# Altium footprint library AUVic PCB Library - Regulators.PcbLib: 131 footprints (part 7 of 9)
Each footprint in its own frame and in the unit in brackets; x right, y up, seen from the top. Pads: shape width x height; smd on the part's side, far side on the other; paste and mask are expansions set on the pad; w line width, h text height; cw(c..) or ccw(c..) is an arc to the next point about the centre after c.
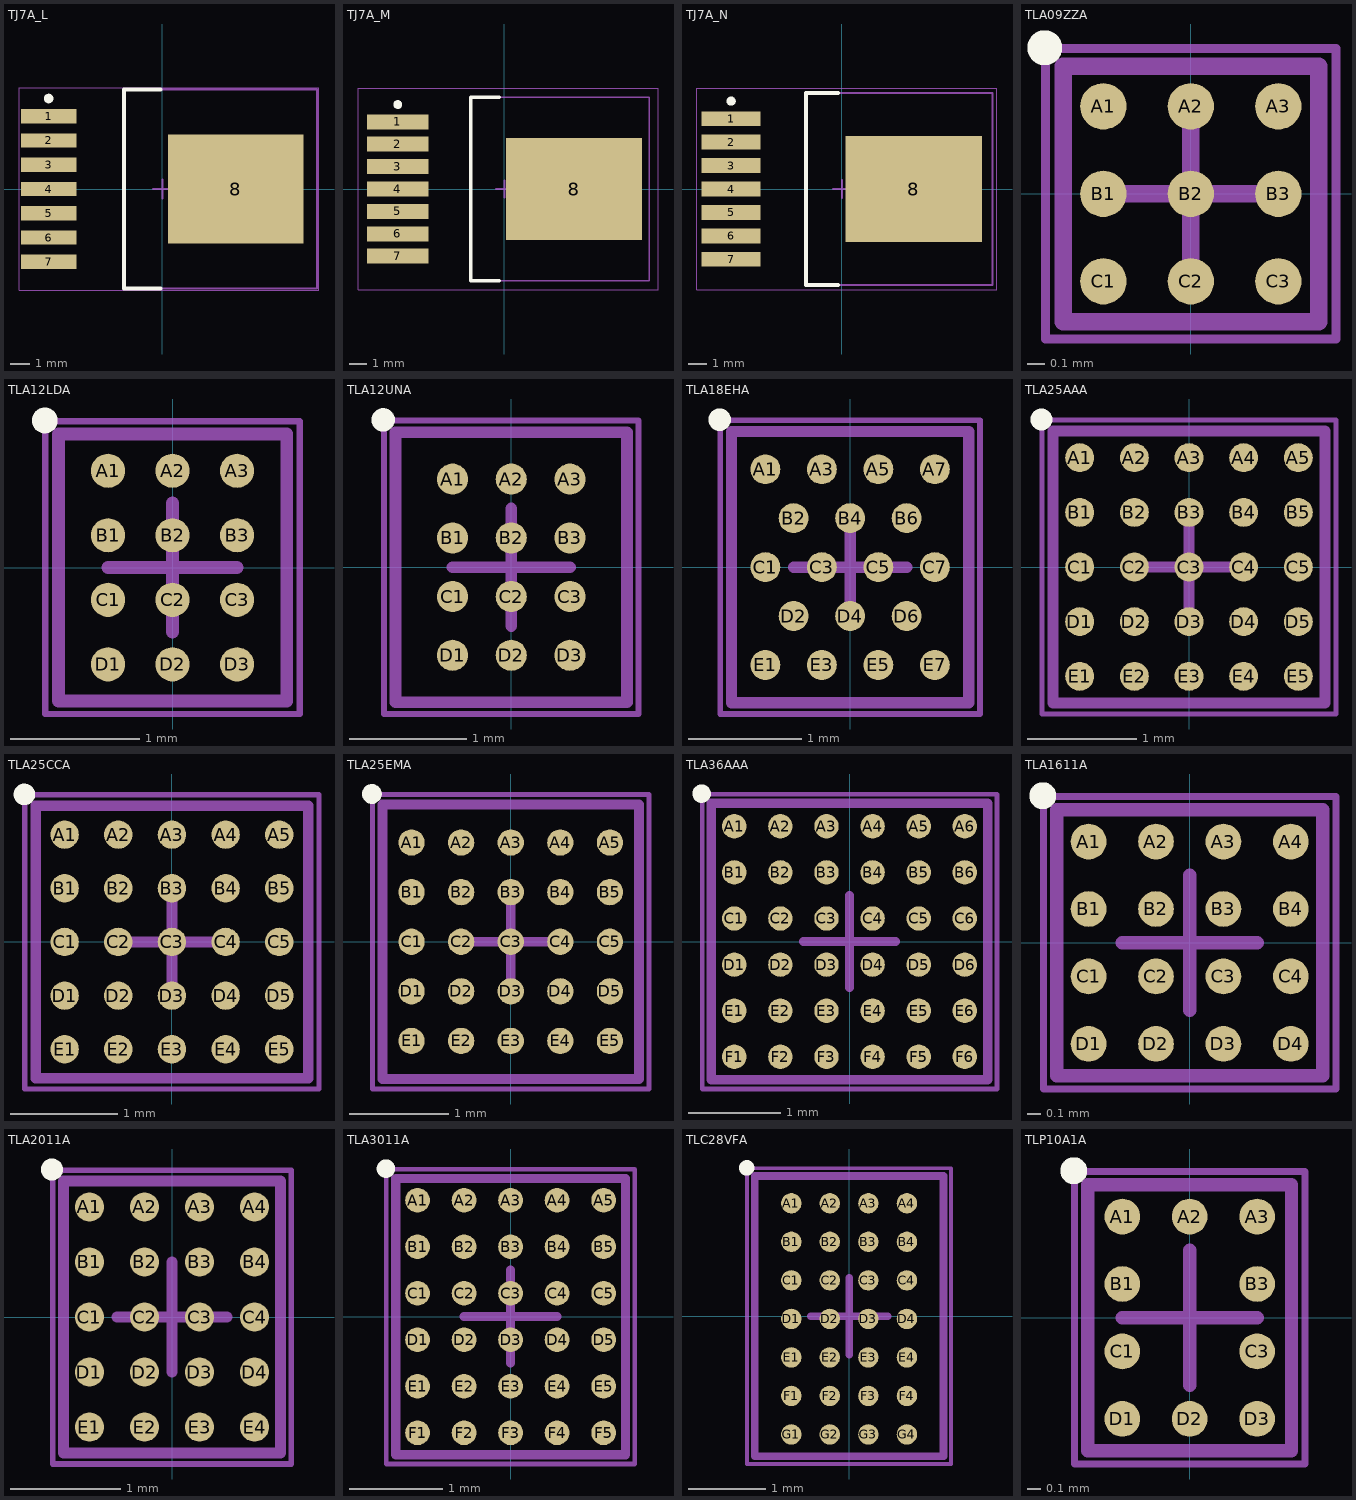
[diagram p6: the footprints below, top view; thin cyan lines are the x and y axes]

## TJ7A_L [mm] "D2-PAK, 8-Leads, Body 9.9x10.2mm, Pitch 1.27mm, Lead Span 14mm, IPC High Density"
height 2.1
pads (8):
  rect 2.9x0.75 smd: 1(-5.95,3.81) 2(-5.95,2.54) 3(-5.95,1.27) 4(-5.95,0) 5(-5.95,-1.27) 6(-5.95,-2.54) 7(-5.95,-3.81)
  rect 7.1x5.7 smd: 8(3.85,0)
Top Overlay:
  circle w0.25: c-5.95,4.735 r0.125
  lines w0.2: -0.1,-5.2 -2,-5.2 -2,5.2 -0.1,5.2
Mechanical 13:
  lines w0.1: -2,-5.2 8.1,-5.2 8.1,5.2 -2,5.2 -2,-5.2
Mechanical 15:
  lines w0.05: -7.5,-5.3 8.2,-5.3 8.2,5.3 -7.5,5.3 -7.5,-5.3
  lines w0.1: -0.5,0 0.5,0 ; 0,-0.5 0,0.5
3D body: height 2.1, standoff 0, extent -2,-5.2 8.1,5.2

## TJ7A_M [mm] "D2-PAK, 8-Leads, Body 9.9x10.2mm, Pitch 1.27mm, Lead Span 14mm, IPC Low Density"
height 2.1
pads (8):
  rect 3.5x0.85 smd: 1(-6.05,3.81) 2(-6.05,2.54) 3(-6.05,1.27) 4(-6.05,0) 5(-6.05,-1.27) 6(-6.05,-2.54) 7(-6.05,-3.81)
  rect 7.7x5.8 smd: 8(3.95,0)
Top Overlay:
  circle w0.25: c-6.05,4.785 r0.125
  lines w0.2: -0.3,-5.2 -1.9,-5.2 -1.9,5.2 -0.3,5.2
Mechanical 13:
  lines w0.1: -1.9,-5.2 8.2,-5.2 8.2,5.2 -1.9,5.2 -1.9,-5.2
Mechanical 15:
  lines w0.05: -8.3,-5.7 8.7,-5.7 8.7,5.7 -8.3,5.7 -8.3,-5.7
  lines w0.1: -0.5,0 0.5,0 ; 0,-0.5 0,0.5
3D body: height 2.1, standoff 0, extent -1.9,-5.2 8.2,5.2

## TJ7A_N [mm] "D2-PAK, 8-Leads, Body 9.9x10.2mm, Pitch 1.27mm, Lead Span 14mm, IPC Medium Density"
height 2.1
pads (8):
  rect 3.2x0.8 smd: 1(-6,3.81) 2(-6,2.54) 3(-6,1.27) 4(-6,0) 5(-6,-1.27) 6(-6,-2.54) 7(-6,-3.81)
  rect 7.4x5.75 smd: 8(3.9,0)
Top Overlay:
  circle w0.25: c-6,4.76 r0.125
  lines w0.2: -0.2,-5.2 -1.95,-5.2 -1.95,5.2 -0.2,5.2
Mechanical 13:
  lines w0.1: -1.95,-5.2 8.15,-5.2 8.15,5.2 -1.95,5.2 -1.95,-5.2
Mechanical 15:
  lines w0.05: -7.85,-5.45 8.4,-5.45 8.4,5.45 -7.85,5.45 -7.85,-5.45
  lines w0.1: -0.5,0 0.5,0 ; 0,-0.5 0,0.5
3D body: height 2.1, standoff 0, extent -1.95,-5.2 8.15,5.2

## TLA09ZZA [mm] "Micro SMD, 9-Leads, Body 1.47x1.47mm, Pitch 0.5mm, NSC Recommended"
height 0.68
pads (9):
  round 0.265 smd paste-0.132 mask+0.05: A1(-0.5,0.5) A2(0,0.5) A3(0.5,0.5) B1(-0.5,0) B2(0,0) B3(0.5,0) C1(-0.5,-0.5) C2(0,-0.5) C3(0.5,-0.5)
Top Overlay:
  circle w0.1: c-0.835,0.835 r0.05
Top Paste:
  circle w0.05: c-0.575,0.425 r0.025
  circle w0.05: c-0.425,0.575 r0.025
  circle w0.05: c-0.425,0.425 r0.025
  circle w0.05: c-0.575,0.575 r0.025
  circle w0.05: c-0.075,0.425 r0.025
  circle w0.05: c0.075,0.575 r0.025
  circle w0.05: c0.075,0.425 r0.025
  circle w0.05: c-0.075,0.575 r0.025
  circle w0.05: c0.425,0.425 r0.025
  circle w0.05: c0.575,0.575 r0.025
  circle w0.05: c0.575,0.425 r0.025
  circle w0.05: c0.425,0.575 r0.025
  circle w0.05: c-0.575,-0.075 r0.025
  circle w0.05: c-0.425,0.075 r0.025
  circle w0.05: c-0.425,-0.075 r0.025
  circle w0.05: c-0.575,0.075 r0.025
  circle w0.05: c-0.075,-0.075 r0.025
  circle w0.05: c0.075,0.075 r0.025
  circle w0.05: c0.075,-0.075 r0.025
  circle w0.05: c-0.075,0.075 r0.025
  circle w0.05: c0.425,-0.075 r0.025
  circle w0.05: c0.575,0.075 r0.025
  circle w0.05: c0.575,-0.075 r0.025
  circle w0.05: c0.425,0.075 r0.025
  circle w0.05: c-0.575,-0.575 r0.025
  circle w0.05: c-0.425,-0.425 r0.025
  circle w0.05: c-0.425,-0.575 r0.025
  circle w0.05: c-0.575,-0.425 r0.025
  circle w0.05: c-0.075,-0.575 r0.025
  circle w0.05: c0.075,-0.425 r0.025
  circle w0.05: c0.075,-0.575 r0.025
  circle w0.05: c-0.075,-0.425 r0.025
  circle w0.05: c0.425,-0.575 r0.025
  circle w0.05: c0.575,-0.425 r0.025
  circle w0.05: c0.575,-0.575 r0.025
  circle w0.05: c0.425,-0.425 r0.025
  region: -0.575,0.575 -0.575,0.425 -0.425,0.425 -0.425,0.575
  region: -0.575,0.425 -0.575,0.575 -0.625,0.575 -0.625,0.425
  rectangle: -0.575,0.575 -0.425,0.625
  region: -0.425,0.575 -0.425,0.425 -0.375,0.425 -0.375,0.575
  region: -0.425,0.425 -0.575,0.425 -0.575,0.375 -0.425,0.375
  region: -0.075,0.575 -0.075,0.425 0.075,0.425 0.075,0.575
  region: -0.075,0.425 -0.075,0.575 -0.125,0.575 -0.125,0.425
  rectangle: -0.075,0.575 0.075,0.625
  region: 0.075,0.575 0.075,0.425 0.125,0.425 0.125,0.575
  region: 0.075,0.425 -0.075,0.425 -0.075,0.375 0.075,0.375
  region: 0.425,0.575 0.425,0.425 0.575,0.425 0.575,0.575
  region: 0.425,0.425 0.425,0.575 0.375,0.575 0.375,0.425
  rectangle: 0.425,0.575 0.575,0.625
  region: 0.575,0.575 0.575,0.425 0.625,0.425 0.625,0.575
  region: 0.575,0.425 0.425,0.425 0.425,0.375 0.575,0.375
  region: -0.575,0.075 -0.575,-0.075 -0.425,-0.075 -0.425,0.075
  region: -0.575,-0.075 -0.575,0.075 -0.625,0.075 -0.625,-0.075
  rectangle: -0.575,0.075 -0.425,0.125
  region: -0.425,0.075 -0.425,-0.075 -0.375,-0.075 -0.375,0.075
  region: -0.425,-0.075 -0.575,-0.075 -0.575,-0.125 -0.425,-0.125
  region: -0.075,0.075 -0.075,-0.075 0.075,-0.075 0.075,0.075
  region: -0.075,-0.075 -0.075,0.075 -0.125,0.075 -0.125,-0.075
  rectangle: -0.075,0.075 0.075,0.125
  region: 0.075,0.075 0.075,-0.075 0.125,-0.075 0.125,0.075
  region: 0.075,-0.075 -0.075,-0.075 -0.075,-0.125 0.075,-0.125
  region: 0.425,0.075 0.425,-0.075 0.575,-0.075 0.575,0.075
  region: 0.425,-0.075 0.425,0.075 0.375,0.075 0.375,-0.075
  rectangle: 0.425,0.075 0.575,0.125
  region: 0.575,0.075 0.575,-0.075 0.625,-0.075 0.625,0.075
  region: 0.575,-0.075 0.425,-0.075 0.425,-0.125 0.575,-0.125
  region: -0.575,-0.425 -0.575,-0.575 -0.425,-0.575 -0.425,-0.425
  region: -0.575,-0.575 -0.575,-0.425 -0.625,-0.425 -0.625,-0.575
  rectangle: -0.575,-0.425 -0.425,-0.375
  region: -0.425,-0.425 -0.425,-0.575 -0.375,-0.575 -0.375,-0.425
  region: -0.425,-0.575 -0.575,-0.575 -0.575,-0.625 -0.425,-0.625
  region: -0.075,-0.425 -0.075,-0.575 0.075,-0.575 0.075,-0.425
  region: -0.075,-0.575 -0.075,-0.425 -0.125,-0.425 -0.125,-0.575
  rectangle: -0.075,-0.425 0.075,-0.375
  region: 0.075,-0.425 0.075,-0.575 0.125,-0.575 0.125,-0.425
  region: 0.075,-0.575 -0.075,-0.575 -0.075,-0.625 0.075,-0.625
  region: 0.425,-0.425 0.425,-0.575 0.575,-0.575 0.575,-0.425
  region: 0.425,-0.575 0.425,-0.425 0.375,-0.425 0.375,-0.575
  rectangle: 0.425,-0.425 0.575,-0.375
  region: 0.575,-0.425 0.575,-0.575 0.625,-0.575 0.625,-0.425
  region: 0.575,-0.575 0.425,-0.575 0.425,-0.625 0.575,-0.625
Mechanical 13:
  lines w0.1: -0.73,-0.73 -0.73,0.73 0.73,0.73 0.73,-0.73 -0.73,-0.73
Mechanical 15:
  lines w0.05: -0.83,-0.83 -0.83,0.83 0.83,0.83 0.83,-0.83 -0.83,-0.83
  lines w0.1: -0.5,0 0.5,0 ; 0,-0.5 0,0.5
3D body: height 0.68, standoff 0, extent -0.73,-0.73 0.73,0.73

## TLA12LDA [mm] "Micro SMD, 12-Leads, Body 2.07x1.77mm, Pitch 0.5mm, NSC Recommended"
height 0.68
pads (12):
  round 0.265 smd paste-0.132 mask+0.05: A1(-0.5,0.75) A2(0,0.75) A3(0.5,0.75) B1(-0.5,0.25) B2(0,0.25) B3(0.5,0.25) C1(-0.5,-0.25) C2(0,-0.25) C3(0.5,-0.25) D1(-0.5,-0.75) D2(0,-0.75) D3(0.5,-0.75)
Top Overlay:
  circle w0.1: c-0.99,1.14 r0.05
Top Paste:
  circle w0.05: c-0.575,0.675 r0.025
  circle w0.05: c-0.425,0.825 r0.025
  circle w0.05: c-0.425,0.675 r0.025
  circle w0.05: c-0.575,0.825 r0.025
  circle w0.05: c-0.075,0.675 r0.025
  circle w0.05: c0.075,0.825 r0.025
  circle w0.05: c0.075,0.675 r0.025
  circle w0.05: c-0.075,0.825 r0.025
  circle w0.05: c0.425,0.675 r0.025
  circle w0.05: c0.575,0.825 r0.025
  circle w0.05: c0.575,0.675 r0.025
  circle w0.05: c0.425,0.825 r0.025
  circle w0.05: c-0.575,0.175 r0.025
  circle w0.05: c-0.425,0.325 r0.025
  circle w0.05: c-0.425,0.175 r0.025
  circle w0.05: c-0.575,0.325 r0.025
  circle w0.05: c-0.075,0.175 r0.025
  circle w0.05: c0.075,0.325 r0.025
  circle w0.05: c0.075,0.175 r0.025
  circle w0.05: c-0.075,0.325 r0.025
  circle w0.05: c0.425,0.175 r0.025
  circle w0.05: c0.575,0.325 r0.025
  circle w0.05: c0.575,0.175 r0.025
  circle w0.05: c0.425,0.325 r0.025
  circle w0.05: c-0.575,-0.325 r0.025
  circle w0.05: c-0.425,-0.175 r0.025
  circle w0.05: c-0.425,-0.325 r0.025
  circle w0.05: c-0.575,-0.175 r0.025
  circle w0.05: c-0.075,-0.325 r0.025
  circle w0.05: c0.075,-0.175 r0.025
  circle w0.05: c0.075,-0.325 r0.025
  circle w0.05: c-0.075,-0.175 r0.025
  circle w0.05: c0.425,-0.325 r0.025
  circle w0.05: c0.575,-0.175 r0.025
  circle w0.05: c0.575,-0.325 r0.025
  circle w0.05: c0.425,-0.175 r0.025
  circle w0.05: c-0.575,-0.825 r0.025
  circle w0.05: c-0.425,-0.675 r0.025
  circle w0.05: c-0.425,-0.825 r0.025
  circle w0.05: c-0.575,-0.675 r0.025
  circle w0.05: c-0.075,-0.825 r0.025
  circle w0.05: c0.075,-0.675 r0.025
  circle w0.05: c0.075,-0.825 r0.025
  circle w0.05: c-0.075,-0.675 r0.025
  circle w0.05: c0.425,-0.825 r0.025
  circle w0.05: c0.575,-0.675 r0.025
  circle w0.05: c0.575,-0.825 r0.025
  circle w0.05: c0.425,-0.675 r0.025
  region: -0.575,0.825 -0.575,0.675 -0.425,0.675 -0.425,0.825
  region: -0.575,0.675 -0.575,0.825 -0.625,0.825 -0.625,0.675
  rectangle: -0.575,0.825 -0.425,0.875
  region: -0.425,0.825 -0.425,0.675 -0.375,0.675 -0.375,0.825
  region: -0.425,0.675 -0.575,0.675 -0.575,0.625 -0.425,0.625
  region: -0.075,0.825 -0.075,0.675 0.075,0.675 0.075,0.825
  region: -0.075,0.675 -0.075,0.825 -0.125,0.825 -0.125,0.675
  rectangle: -0.075,0.825 0.075,0.875
  region: 0.075,0.825 0.075,0.675 0.125,0.675 0.125,0.825
  region: 0.075,0.675 -0.075,0.675 -0.075,0.625 0.075,0.625
  region: 0.425,0.825 0.425,0.675 0.575,0.675 0.575,0.825
  region: 0.425,0.675 0.425,0.825 0.375,0.825 0.375,0.675
  rectangle: 0.425,0.825 0.575,0.875
  region: 0.575,0.825 0.575,0.675 0.625,0.675 0.625,0.825
  region: 0.575,0.675 0.425,0.675 0.425,0.625 0.575,0.625
  region: -0.575,0.325 -0.575,0.175 -0.425,0.175 -0.425,0.325
  region: -0.575,0.175 -0.575,0.325 -0.625,0.325 -0.625,0.175
  rectangle: -0.575,0.325 -0.425,0.375
  region: -0.425,0.325 -0.425,0.175 -0.375,0.175 -0.375,0.325
  region: -0.425,0.175 -0.575,0.175 -0.575,0.125 -0.425,0.125
  region: -0.075,0.325 -0.075,0.175 0.075,0.175 0.075,0.325
  region: -0.075,0.175 -0.075,0.325 -0.125,0.325 -0.125,0.175
  rectangle: -0.075,0.325 0.075,0.375
  region: 0.075,0.325 0.075,0.175 0.125,0.175 0.125,0.325
  region: 0.075,0.175 -0.075,0.175 -0.075,0.125 0.075,0.125
  region: 0.425,0.325 0.425,0.175 0.575,0.175 0.575,0.325
  region: 0.425,0.175 0.425,0.325 0.375,0.325 0.375,0.175
  rectangle: 0.425,0.325 0.575,0.375
  region: 0.575,0.325 0.575,0.175 0.625,0.175 0.625,0.325
  region: 0.575,0.175 0.425,0.175 0.425,0.125 0.575,0.125
  region: -0.575,-0.175 -0.575,-0.325 -0.425,-0.325 -0.425,-0.175
  region: -0.575,-0.325 -0.575,-0.175 -0.625,-0.175 -0.625,-0.325
  rectangle: -0.575,-0.175 -0.425,-0.125
  region: -0.425,-0.175 -0.425,-0.325 -0.375,-0.325 -0.375,-0.175
  region: -0.425,-0.325 -0.575,-0.325 -0.575,-0.375 -0.425,-0.375
  region: -0.075,-0.175 -0.075,-0.325 0.075,-0.325 0.075,-0.175
  region: -0.075,-0.325 -0.075,-0.175 -0.125,-0.175 -0.125,-0.325
  rectangle: -0.075,-0.175 0.075,-0.125
  region: 0.075,-0.175 0.075,-0.325 0.125,-0.325 0.125,-0.175
  region: 0.075,-0.325 -0.075,-0.325 -0.075,-0.375 0.075,-0.375
  region: 0.425,-0.175 0.425,-0.325 0.575,-0.325 0.575,-0.175
  region: 0.425,-0.325 0.425,-0.175 0.375,-0.175 0.375,-0.325
  rectangle: 0.425,-0.175 0.575,-0.125
  region: 0.575,-0.175 0.575,-0.325 0.625,-0.325 0.625,-0.175
  region: 0.575,-0.325 0.425,-0.325 0.425,-0.375 0.575,-0.375
  region: -0.575,-0.675 -0.575,-0.825 -0.425,-0.825 -0.425,-0.675
  region: -0.575,-0.825 -0.575,-0.675 -0.625,-0.675 -0.625,-0.825
  rectangle: -0.575,-0.675 -0.425,-0.625
  region: -0.425,-0.675 -0.425,-0.825 -0.375,-0.825 -0.375,-0.675
  region: -0.425,-0.825 -0.575,-0.825 -0.575,-0.875 -0.425,-0.875
  region: -0.075,-0.675 -0.075,-0.825 0.075,-0.825 0.075,-0.675
  region: -0.075,-0.825 -0.075,-0.675 -0.125,-0.675 -0.125,-0.825
  rectangle: -0.075,-0.675 0.075,-0.625
  region: 0.075,-0.675 0.075,-0.825 0.125,-0.825 0.125,-0.675
  region: 0.075,-0.825 -0.075,-0.825 -0.075,-0.875 0.075,-0.875
  region: 0.425,-0.675 0.425,-0.825 0.575,-0.825 0.575,-0.675
  region: 0.425,-0.825 0.425,-0.675 0.375,-0.675 0.375,-0.825
  rectangle: 0.425,-0.675 0.575,-0.625
  region: 0.575,-0.675 0.575,-0.825 0.625,-0.825 0.625,-0.675
  region: 0.575,-0.825 0.425,-0.825 0.425,-0.875 0.575,-0.875
Mechanical 13:
  lines w0.1: -0.885,-1.035 -0.885,1.035 0.885,1.035 0.885,-1.035 -0.885,-1.035
Mechanical 15:
  lines w0.05: -0.985,-1.135 -0.985,1.135 0.985,1.135 0.985,-1.135 -0.985,-1.135
  lines w0.1: -0.5,0 0.5,0 ; 0,-0.5 0,0.5
3D body: height 0.68, standoff 0, extent -0.885,-1.035 0.885,1.035

## TLA12UNA [mm] "Micro SMD, 12-Leads, Body 2.3x1.97mm, Pitch 0.5mm, NSC Recommended"
height 0.68
pads (12):
  round 0.265 smd paste-0.132 mask+0.05: A1(-0.5,0.75) A2(0,0.75) A3(0.5,0.75) B1(-0.5,0.25) B2(0,0.25) B3(0.5,0.25) C1(-0.5,-0.25) C2(0,-0.25) C3(0.5,-0.25) D1(-0.5,-0.75) D2(0,-0.75) D3(0.5,-0.75)
Top Overlay:
  circle w0.1: c-1.09,1.255 r0.05
Top Paste:
  circle w0.05: c-0.575,0.675 r0.025
  circle w0.05: c-0.425,0.825 r0.025
  circle w0.05: c-0.425,0.675 r0.025
  circle w0.05: c-0.575,0.825 r0.025
  circle w0.05: c-0.075,0.675 r0.025
  circle w0.05: c0.075,0.825 r0.025
  circle w0.05: c0.075,0.675 r0.025
  circle w0.05: c-0.075,0.825 r0.025
  circle w0.05: c0.425,0.675 r0.025
  circle w0.05: c0.575,0.825 r0.025
  circle w0.05: c0.575,0.675 r0.025
  circle w0.05: c0.425,0.825 r0.025
  circle w0.05: c-0.575,0.175 r0.025
  circle w0.05: c-0.425,0.325 r0.025
  circle w0.05: c-0.425,0.175 r0.025
  circle w0.05: c-0.575,0.325 r0.025
  circle w0.05: c-0.075,0.175 r0.025
  circle w0.05: c0.075,0.325 r0.025
  circle w0.05: c0.075,0.175 r0.025
  circle w0.05: c-0.075,0.325 r0.025
  circle w0.05: c0.425,0.175 r0.025
  circle w0.05: c0.575,0.325 r0.025
  circle w0.05: c0.575,0.175 r0.025
  circle w0.05: c0.425,0.325 r0.025
  circle w0.05: c-0.575,-0.325 r0.025
  circle w0.05: c-0.425,-0.175 r0.025
  circle w0.05: c-0.425,-0.325 r0.025
  circle w0.05: c-0.575,-0.175 r0.025
  circle w0.05: c-0.075,-0.325 r0.025
  circle w0.05: c0.075,-0.175 r0.025
  circle w0.05: c0.075,-0.325 r0.025
  circle w0.05: c-0.075,-0.175 r0.025
  circle w0.05: c0.425,-0.325 r0.025
  circle w0.05: c0.575,-0.175 r0.025
  circle w0.05: c0.575,-0.325 r0.025
  circle w0.05: c0.425,-0.175 r0.025
  circle w0.05: c-0.575,-0.825 r0.025
  circle w0.05: c-0.425,-0.675 r0.025
  circle w0.05: c-0.425,-0.825 r0.025
  circle w0.05: c-0.575,-0.675 r0.025
  circle w0.05: c-0.075,-0.825 r0.025
  circle w0.05: c0.075,-0.675 r0.025
  circle w0.05: c0.075,-0.825 r0.025
  circle w0.05: c-0.075,-0.675 r0.025
  circle w0.05: c0.425,-0.825 r0.025
  circle w0.05: c0.575,-0.675 r0.025
  circle w0.05: c0.575,-0.825 r0.025
  circle w0.05: c0.425,-0.675 r0.025
  region: -0.575,0.825 -0.575,0.675 -0.425,0.675 -0.425,0.825
  region: -0.575,0.675 -0.575,0.825 -0.625,0.825 -0.625,0.675
  rectangle: -0.575,0.825 -0.425,0.875
  region: -0.425,0.825 -0.425,0.675 -0.375,0.675 -0.375,0.825
  region: -0.425,0.675 -0.575,0.675 -0.575,0.625 -0.425,0.625
  region: -0.075,0.825 -0.075,0.675 0.075,0.675 0.075,0.825
  region: -0.075,0.675 -0.075,0.825 -0.125,0.825 -0.125,0.675
  rectangle: -0.075,0.825 0.075,0.875
  region: 0.075,0.825 0.075,0.675 0.125,0.675 0.125,0.825
  region: 0.075,0.675 -0.075,0.675 -0.075,0.625 0.075,0.625
  region: 0.425,0.825 0.425,0.675 0.575,0.675 0.575,0.825
  region: 0.425,0.675 0.425,0.825 0.375,0.825 0.375,0.675
  rectangle: 0.425,0.825 0.575,0.875
  region: 0.575,0.825 0.575,0.675 0.625,0.675 0.625,0.825
  region: 0.575,0.675 0.425,0.675 0.425,0.625 0.575,0.625
  region: -0.575,0.325 -0.575,0.175 -0.425,0.175 -0.425,0.325
  region: -0.575,0.175 -0.575,0.325 -0.625,0.325 -0.625,0.175
  rectangle: -0.575,0.325 -0.425,0.375
  region: -0.425,0.325 -0.425,0.175 -0.375,0.175 -0.375,0.325
  region: -0.425,0.175 -0.575,0.175 -0.575,0.125 -0.425,0.125
  region: -0.075,0.325 -0.075,0.175 0.075,0.175 0.075,0.325
  region: -0.075,0.175 -0.075,0.325 -0.125,0.325 -0.125,0.175
  rectangle: -0.075,0.325 0.075,0.375
  region: 0.075,0.325 0.075,0.175 0.125,0.175 0.125,0.325
  region: 0.075,0.175 -0.075,0.175 -0.075,0.125 0.075,0.125
  region: 0.425,0.325 0.425,0.175 0.575,0.175 0.575,0.325
  region: 0.425,0.175 0.425,0.325 0.375,0.325 0.375,0.175
  rectangle: 0.425,0.325 0.575,0.375
  region: 0.575,0.325 0.575,0.175 0.625,0.175 0.625,0.325
  region: 0.575,0.175 0.425,0.175 0.425,0.125 0.575,0.125
  region: -0.575,-0.175 -0.575,-0.325 -0.425,-0.325 -0.425,-0.175
  region: -0.575,-0.325 -0.575,-0.175 -0.625,-0.175 -0.625,-0.325
  rectangle: -0.575,-0.175 -0.425,-0.125
  region: -0.425,-0.175 -0.425,-0.325 -0.375,-0.325 -0.375,-0.175
  region: -0.425,-0.325 -0.575,-0.325 -0.575,-0.375 -0.425,-0.375
  region: -0.075,-0.175 -0.075,-0.325 0.075,-0.325 0.075,-0.175
  region: -0.075,-0.325 -0.075,-0.175 -0.125,-0.175 -0.125,-0.325
  rectangle: -0.075,-0.175 0.075,-0.125
  region: 0.075,-0.175 0.075,-0.325 0.125,-0.325 0.125,-0.175
  region: 0.075,-0.325 -0.075,-0.325 -0.075,-0.375 0.075,-0.375
  region: 0.425,-0.175 0.425,-0.325 0.575,-0.325 0.575,-0.175
  region: 0.425,-0.325 0.425,-0.175 0.375,-0.175 0.375,-0.325
  rectangle: 0.425,-0.175 0.575,-0.125
  region: 0.575,-0.175 0.575,-0.325 0.625,-0.325 0.625,-0.175
  region: 0.575,-0.325 0.425,-0.325 0.425,-0.375 0.575,-0.375
  region: -0.575,-0.675 -0.575,-0.825 -0.425,-0.825 -0.425,-0.675
  region: -0.575,-0.825 -0.575,-0.675 -0.625,-0.675 -0.625,-0.825
  rectangle: -0.575,-0.675 -0.425,-0.625
  region: -0.425,-0.675 -0.425,-0.825 -0.375,-0.825 -0.375,-0.675
  region: -0.425,-0.825 -0.575,-0.825 -0.575,-0.875 -0.425,-0.875
  region: -0.075,-0.675 -0.075,-0.825 0.075,-0.825 0.075,-0.675
  region: -0.075,-0.825 -0.075,-0.675 -0.125,-0.675 -0.125,-0.825
  rectangle: -0.075,-0.675 0.075,-0.625
  region: 0.075,-0.675 0.075,-0.825 0.125,-0.825 0.125,-0.675
  region: 0.075,-0.825 -0.075,-0.825 -0.075,-0.875 0.075,-0.875
  region: 0.425,-0.675 0.425,-0.825 0.575,-0.825 0.575,-0.675
  region: 0.425,-0.825 0.425,-0.675 0.375,-0.675 0.375,-0.825
  rectangle: 0.425,-0.675 0.575,-0.625
  region: 0.575,-0.675 0.575,-0.825 0.625,-0.825 0.625,-0.675
  region: 0.575,-0.825 0.425,-0.825 0.425,-0.875 0.575,-0.875
Mechanical 13:
  lines w0.1: -0.985,-1.15 -0.985,1.15 0.985,1.15 0.985,-1.15 -0.985,-1.15
Mechanical 15:
  lines w0.05: -1.085,-1.25 -1.085,1.25 1.085,1.25 1.085,-1.25 -1.085,-1.25
  lines w0.1: -0.5,0 0.5,0 ; 0,-0.5 0,0.5
3D body: height 0.68, standoff 0, extent -0.985,-1.15 0.985,1.15

## TLA18EHA [mm] "Micro SMD, 18-Leads, Body 2.41x2.1mm, Pitch 0.5mm, NSC Recommended"
height 0.68
pads (18):
  round 0.265 smd paste-0.132 mask+0.05: A1(-0.75,0.866) A3(-0.25,0.866) A5(0.25,0.866) A7(0.75,0.866) B2(-0.5,0.433) B4(0,0.433) B6(0.5,0.433) C1(-0.75,0) C3(-0.25,0) C5(0.25,0) C7(0.75,0) D2(-0.5,-0.433) D4(0,-0.433) D6(0.5,-0.433) E1(-0.75,-0.866) E3(-0.25,-0.866) E5(0.25,-0.866) E7(0.75,-0.866)
Top Overlay:
  circle w0.1: c-1.155,1.305 r0.05
Top Paste:
  drawing of 162 lines, arcs and shapes, not listed
Mechanical 13:
  lines w0.1: -1.05,-1.2 1.05,-1.2 1.05,1.2 -1.05,1.2 -1.05,-1.2
Mechanical 15:
  lines w0.05: -1.15,-1.3 -1.15,1.3 1.15,1.3 1.15,-1.3 -1.15,-1.3
  lines w0.1: -0.5,0 0.5,0 ; 0,-0.5 0,0.5
3D body: height 0.68, standoff 0, extent -1.049,-1.2 1.049,1.199

## TLA25AAA [mm] "Micro SMD, 25-Leads, Body 2.49x2.49mm, Pitch 0.5mm, NSC Recommended"
height 0.68
pads (25):
  round 0.265 smd paste-0.132 mask+0.05: A1(-1,1) A2(-0.5,1) A3(0,1) A4(0.5,1) A5(1,1) B1(-1,0.5) B2(-0.5,0.5) B3(0,0.5) B4(0.5,0.5) B5(1,0.5) C1(-1,0) C2(-0.5,0) C3(0,0) C4(0.5,0) C5(1,0) D1(-1,-0.5) D2(-0.5,-0.5) D3(0,-0.5) D4(0.5,-0.5) D5(1,-0.5) E1(-1,-1) E2(-0.5,-1) E3(0,-1) E4(0.5,-1) E5(1,-1)
Top Overlay:
  circle w0.1: c-1.35,1.35 r0.05
Top Paste:
  drawing of 225 lines, arcs and shapes, not listed
Mechanical 13:
  lines w0.1: -1.245,-1.245 1.245,-1.245 1.245,1.245 -1.245,1.245 -1.245,-1.245
Mechanical 15:
  lines w0.05: -1.345,-1.345 1.345,-1.345 1.345,1.345 -1.345,1.345 -1.345,-1.345
  lines w0.1: -0.5,0 0.5,0 ; 0,-0.5 0,0.5
3D body: height 0.68, standoff 0, extent -1.245,-1.245 1.245,1.245

## TLA25CCA [mm] "Micro SMD, 25-Leads, Body 2.54x2.54mm, Pitch 0.5mm, NSC Recommended"
height 0.68
pads (25):
  round 0.265 smd paste-0.132 mask+0.05: A1(-1,1) A2(-0.5,1) A3(0,1) A4(0.5,1) A5(1,1) B1(-1,0.5) B2(-0.5,0.5) B3(0,0.5) B4(0.5,0.5) B5(1,0.5) C1(-1,0) C2(-0.5,0) C3(0,0) C4(0.5,0) C5(1,0) D1(-1,-0.5) D2(-0.5,-0.5) D3(0,-0.5) D4(0.5,-0.5) D5(1,-0.5) E1(-1,-1) E2(-0.5,-1) E3(0,-1) E4(0.5,-1) E5(1,-1)
Top Overlay:
  circle w0.1: c-1.375,1.375 r0.05
Top Paste:
  drawing of 225 lines, arcs and shapes, not listed
Mechanical 13:
  lines w0.1: -1.27,-1.27 1.27,-1.27 1.27,1.27 -1.27,1.27 -1.27,-1.27
Mechanical 15:
  lines w0.05: -1.37,-1.37 1.37,-1.37 1.37,1.37 -1.37,1.37 -1.37,-1.37
  lines w0.1: -0.5,0 0.5,0 ; 0,-0.5 0,0.5
3D body: height 0.68, standoff 0, extent -1.27,-1.27 1.27,1.27

## TLA25EMA [mm] "Micro SMD, 25-Leads, Body 2.77x2.59mm, Pitch 0.5mm, NSC Recommended"
height 0.68
pads (25):
  round 0.265 smd paste-0.132 mask+0.05: A1(-1,1) A2(-0.5,1) A3(0,1) A4(0.5,1) A5(1,1) B1(-1,0.5) B2(-0.5,0.5) B3(0,0.5) B4(0.5,0.5) B5(1,0.5) C1(-1,0) C2(-0.5,0) C3(0,0) C4(0.5,0) C5(1,0) D1(-1,-0.5) D2(-0.5,-0.5) D3(0,-0.5) D4(0.5,-0.5) D5(1,-0.5) E1(-1,-1) E2(-0.5,-1) E3(0,-1) E4(0.5,-1) E5(1,-1)
Top Overlay:
  circle w0.1: c-1.4,1.49 r0.05
Top Paste:
  drawing of 225 lines, arcs and shapes, not listed
Mechanical 13:
  lines w0.1: -1.295,-1.385 1.295,-1.385 1.295,1.385 -1.295,1.385 -1.295,-1.385
Mechanical 15:
  lines w0.05: -1.395,-1.485 1.395,-1.485 1.395,1.485 -1.395,1.485 -1.395,-1.485
  lines w0.1: -0.5,0 0.5,0 ; 0,-0.5 0,0.5
3D body: height 0.68, standoff 0, extent -1.295,-1.385 1.295,1.385

## TLA36AAA [mm] "Micro SMD, 36-Leads, Body 3x3mm, Pitch 0.5mm, NSC Recommended"
height 0.68
pads (36):
  round 0.265 smd paste-0.132 mask+0.05: A1(-1.25,1.25) A2(-0.75,1.25) A3(-0.25,1.25) A4(0.25,1.25) A5(0.75,1.25) A6(1.25,1.25) B1(-1.25,0.75) B2(-0.75,0.75) B3(-0.25,0.75) B4(0.25,0.75) B5(0.75,0.75) B6(1.25,0.75) C1(-1.25,0.25) C2(-0.75,0.25) C3(-0.25,0.25) C4(0.25,0.25) C5(0.75,0.25) C6(1.25,0.25) D1(-1.25,-0.25) D2(-0.75,-0.25) D3(-0.25,-0.25) D4(0.25,-0.25) D5(0.75,-0.25) D6(1.25,-0.25) E1(-1.25,-0.75) E2(-0.75,-0.75) E3(-0.25,-0.75) E4(0.25,-0.75) E5(0.75,-0.75) E6(1.25,-0.75) F1(-1.25,-1.25) F2(-0.75,-1.25) F3(-0.25,-1.25) F4(0.25,-1.25) F5(0.75,-1.25) F6(1.25,-1.25)
Top Overlay:
  circle w0.1: c-1.605,1.605 r0.05
Top Paste:
  drawing of 324 lines, arcs and shapes, not listed
Mechanical 13:
  lines w0.1: -1.5,-1.5 -1.5,1.5 1.5,1.5 1.5,-1.5 -1.5,-1.5
Mechanical 15:
  lines w0.05: -1.6,-1.6 -1.6,1.6 1.6,1.6 1.6,-1.6 -1.6,-1.6
  lines w0.1: -0.5,0 0.5,0 ; 0,-0.5 0,0.5
3D body: height 0.68, standoff 0, extent -1.5,-1.5 1.5,1.5

## TLA1611A [mm] "Micro SMD, 16-Leads, Body 1.97x1.97mm, Pitch 0.5mm, NSC Recommended"
height 0.68
pads (16):
  round 0.265 smd paste-0.132 mask+0.05: A1(-0.75,0.75) A2(-0.25,0.75) A3(0.25,0.75) A4(0.75,0.75) B1(-0.75,0.25) B2(-0.25,0.25) B3(0.25,0.25) B4(0.75,0.25) C1(-0.75,-0.25) C2(-0.25,-0.25) C3(0.25,-0.25) C4(0.75,-0.25) D1(-0.75,-0.75) D2(-0.25,-0.75) D3(0.25,-0.75) D4(0.75,-0.75)
Top Overlay:
  circle w0.1: c-1.09,1.09 r0.05
Top Paste:
  circle w0.05: c-0.825,0.675 r0.025
  circle w0.05: c-0.675,0.825 r0.025
  circle w0.05: c-0.675,0.675 r0.025
  circle w0.05: c-0.825,0.825 r0.025
  circle w0.05: c-0.325,0.675 r0.025
  circle w0.05: c-0.175,0.825 r0.025
  circle w0.05: c-0.175,0.675 r0.025
  circle w0.05: c-0.325,0.825 r0.025
  circle w0.05: c0.175,0.675 r0.025
  circle w0.05: c0.325,0.825 r0.025
  circle w0.05: c0.325,0.675 r0.025
  circle w0.05: c0.175,0.825 r0.025
  circle w0.05: c0.675,0.675 r0.025
  circle w0.05: c0.825,0.825 r0.025
  circle w0.05: c0.825,0.675 r0.025
  circle w0.05: c0.675,0.825 r0.025
  circle w0.05: c-0.825,0.175 r0.025
  circle w0.05: c-0.675,0.325 r0.025
  circle w0.05: c-0.675,0.175 r0.025
  circle w0.05: c-0.825,0.325 r0.025
  circle w0.05: c-0.325,0.175 r0.025
  circle w0.05: c-0.175,0.325 r0.025
  circle w0.05: c-0.175,0.175 r0.025
  circle w0.05: c-0.325,0.325 r0.025
  circle w0.05: c0.175,0.175 r0.025
  circle w0.05: c0.325,0.325 r0.025
  circle w0.05: c0.325,0.175 r0.025
  circle w0.05: c0.175,0.325 r0.025
  circle w0.05: c0.675,0.175 r0.025
  circle w0.05: c0.825,0.325 r0.025
  circle w0.05: c0.825,0.175 r0.025
  circle w0.05: c0.675,0.325 r0.025
  circle w0.05: c-0.825,-0.325 r0.025
  circle w0.05: c-0.675,-0.175 r0.025
  circle w0.05: c-0.675,-0.325 r0.025
  circle w0.05: c-0.825,-0.175 r0.025
  circle w0.05: c-0.325,-0.325 r0.025
  circle w0.05: c-0.175,-0.175 r0.025
  circle w0.05: c-0.175,-0.325 r0.025
  circle w0.05: c-0.325,-0.175 r0.025
  circle w0.05: c0.175,-0.325 r0.025
  circle w0.05: c0.325,-0.175 r0.025
  circle w0.05: c0.325,-0.325 r0.025
  circle w0.05: c0.175,-0.175 r0.025
  circle w0.05: c0.675,-0.325 r0.025
  circle w0.05: c0.825,-0.175 r0.025
  circle w0.05: c0.825,-0.325 r0.025
  circle w0.05: c0.675,-0.175 r0.025
  circle w0.05: c-0.825,-0.825 r0.025
  circle w0.05: c-0.675,-0.675 r0.025
  circle w0.05: c-0.675,-0.825 r0.025
  circle w0.05: c-0.825,-0.675 r0.025
  circle w0.05: c-0.325,-0.825 r0.025
  circle w0.05: c-0.175,-0.675 r0.025
  circle w0.05: c-0.175,-0.825 r0.025
  circle w0.05: c-0.325,-0.675 r0.025
  circle w0.05: c0.175,-0.825 r0.025
  circle w0.05: c0.325,-0.675 r0.025
  circle w0.05: c0.325,-0.825 r0.025
  circle w0.05: c0.175,-0.675 r0.025
  circle w0.05: c0.675,-0.825 r0.025
  circle w0.05: c0.825,-0.675 r0.025
  circle w0.05: c0.825,-0.825 r0.025
  circle w0.05: c0.675,-0.675 r0.025
  region: -0.825,0.825 -0.825,0.675 -0.675,0.675 -0.675,0.825
  region: -0.825,0.675 -0.825,0.825 -0.875,0.825 -0.875,0.675
  rectangle: -0.825,0.825 -0.675,0.875
  region: -0.675,0.825 -0.675,0.675 -0.625,0.675 -0.625,0.825
  region: -0.675,0.675 -0.825,0.675 -0.825,0.625 -0.675,0.625
  region: -0.325,0.825 -0.325,0.675 -0.175,0.675 -0.175,0.825
  region: -0.325,0.675 -0.325,0.825 -0.375,0.825 -0.375,0.675
  rectangle: -0.325,0.825 -0.175,0.875
  region: -0.175,0.825 -0.175,0.675 -0.125,0.675 -0.125,0.825
  region: -0.175,0.675 -0.325,0.675 -0.325,0.625 -0.175,0.625
  region: 0.175,0.825 0.175,0.675 0.325,0.675 0.325,0.825
  region: 0.175,0.675 0.175,0.825 0.125,0.825 0.125,0.675
  rectangle: 0.175,0.825 0.325,0.875
  region: 0.325,0.825 0.325,0.675 0.375,0.675 0.375,0.825
  region: 0.325,0.675 0.175,0.675 0.175,0.625 0.325,0.625
  region: 0.675,0.825 0.675,0.675 0.825,0.675 0.825,0.825
  region: 0.675,0.675 0.675,0.825 0.625,0.825 0.625,0.675
  rectangle: 0.675,0.825 0.825,0.875
  region: 0.825,0.825 0.825,0.675 0.875,0.675 0.875,0.825
  region: 0.825,0.675 0.675,0.675 0.675,0.625 0.825,0.625
  region: -0.825,0.325 -0.825,0.175 -0.675,0.175 -0.675,0.325
  region: -0.825,0.175 -0.825,0.325 -0.875,0.325 -0.875,0.175
  rectangle: -0.825,0.325 -0.675,0.375
  region: -0.675,0.325 -0.675,0.175 -0.625,0.175 -0.625,0.325
  region: -0.675,0.175 -0.825,0.175 -0.825,0.125 -0.675,0.125
  region: -0.325,0.325 -0.325,0.175 -0.175,0.175 -0.175,0.325
  region: -0.325,0.175 -0.325,0.325 -0.375,0.325 -0.375,0.175
  rectangle: -0.325,0.325 -0.175,0.375
  region: -0.175,0.325 -0.175,0.175 -0.125,0.175 -0.125,0.325
  region: -0.175,0.175 -0.325,0.175 -0.325,0.125 -0.175,0.125
  region: 0.175,0.325 0.175,0.175 0.325,0.175 0.325,0.325
  region: 0.175,0.175 0.175,0.325 0.125,0.325 0.125,0.175
  rectangle: 0.175,0.325 0.325,0.375
  region: 0.325,0.325 0.325,0.175 0.375,0.175 0.375,0.325
  region: 0.325,0.175 0.175,0.175 0.175,0.125 0.325,0.125
  region: 0.675,0.325 0.675,0.175 0.825,0.175 0.825,0.325
  region: 0.675,0.175 0.675,0.325 0.625,0.325 0.625,0.175
  rectangle: 0.675,0.325 0.825,0.375
  region: 0.825,0.325 0.825,0.175 0.875,0.175 0.875,0.325
  region: 0.825,0.175 0.675,0.175 0.675,0.125 0.825,0.125
  region: -0.825,-0.175 -0.825,-0.325 -0.675,-0.325 -0.675,-0.175
  region: -0.825,-0.325 -0.825,-0.175 -0.875,-0.175 -0.875,-0.325
  rectangle: -0.825,-0.175 -0.675,-0.125
  region: -0.675,-0.175 -0.675,-0.325 -0.625,-0.325 -0.625,-0.175
  region: -0.675,-0.325 -0.825,-0.325 -0.825,-0.375 -0.675,-0.375
  region: -0.325,-0.175 -0.325,-0.325 -0.175,-0.325 -0.175,-0.175
  region: -0.325,-0.325 -0.325,-0.175 -0.375,-0.175 -0.375,-0.325
  rectangle: -0.325,-0.175 -0.175,-0.125
  region: -0.175,-0.175 -0.175,-0.325 -0.125,-0.325 -0.125,-0.175
  region: -0.175,-0.325 -0.325,-0.325 -0.325,-0.375 -0.175,-0.375
  region: 0.175,-0.175 0.175,-0.325 0.325,-0.325 0.325,-0.175
  region: 0.175,-0.325 0.175,-0.175 0.125,-0.175 0.125,-0.325
  rectangle: 0.175,-0.175 0.325,-0.125
  region: 0.325,-0.175 0.325,-0.325 0.375,-0.325 0.375,-0.175
  region: 0.325,-0.325 0.175,-0.325 0.175,-0.375 0.325,-0.375
  region: 0.675,-0.175 0.675,-0.325 0.825,-0.325 0.825,-0.175
  region: 0.675,-0.325 0.675,-0.175 0.625,-0.175 0.625,-0.325
  rectangle: 0.675,-0.175 0.825,-0.125
  region: 0.825,-0.175 0.825,-0.325 0.875,-0.325 0.875,-0.175
  region: 0.825,-0.325 0.675,-0.325 0.675,-0.375 0.825,-0.375
  region: -0.825,-0.675 -0.825,-0.825 -0.675,-0.825 -0.675,-0.675
  region: -0.825,-0.825 -0.825,-0.675 -0.875,-0.675 -0.875,-0.825
  rectangle: -0.825,-0.675 -0.675,-0.625
  region: -0.675,-0.675 -0.675,-0.825 -0.625,-0.825 -0.625,-0.675
  region: -0.675,-0.825 -0.825,-0.825 -0.825,-0.875 -0.675,-0.875
  region: -0.325,-0.675 -0.325,-0.825 -0.175,-0.825 -0.175,-0.675
  region: -0.325,-0.825 -0.325,-0.675 -0.375,-0.675 -0.375,-0.825
  rectangle: -0.325,-0.675 -0.175,-0.625
  region: -0.175,-0.675 -0.175,-0.825 -0.125,-0.825 -0.125,-0.675
  region: -0.175,-0.825 -0.325,-0.825 -0.325,-0.875 -0.175,-0.875
  region: 0.175,-0.675 0.175,-0.825 0.325,-0.825 0.325,-0.675
  region: 0.175,-0.825 0.175,-0.675 0.125,-0.675 0.125,-0.825
  rectangle: 0.175,-0.675 0.325,-0.625
  region: 0.325,-0.675 0.325,-0.825 0.375,-0.825 0.375,-0.675
  region: 0.325,-0.825 0.175,-0.825 0.175,-0.875 0.325,-0.875
  region: 0.675,-0.675 0.675,-0.825 0.825,-0.825 0.825,-0.675
  region: 0.675,-0.825 0.675,-0.675 0.625,-0.675 0.625,-0.825
  rectangle: 0.675,-0.675 0.825,-0.625
  region: 0.825,-0.675 0.825,-0.825 0.875,-0.825 0.875,-0.675
  region: 0.825,-0.825 0.675,-0.825 0.675,-0.875 0.825,-0.875
Mechanical 13:
  lines w0.1: -0.985,-0.985 -0.985,0.985 0.985,0.985 0.985,-0.985 -0.985,-0.985
Mechanical 15:
  lines w0.05: -1.085,-1.085 -1.085,1.085 1.085,1.085 1.085,-1.085 -1.085,-1.085
  lines w0.1: -0.5,0 0.5,0 ; 0,-0.5 0,0.5
3D body: height 0.68, standoff 0, extent -0.985,-0.985 0.985,0.985

## TLA2011A [mm] "Micro SMD, 20-Leads, Body 2.47x1.97mm, Pitch 0.5mm, NSC Recommended"
height 0.68
pads (20):
  round 0.265 smd paste-0.132 mask+0.05: A1(-0.75,1) A2(-0.25,1) A3(0.25,1) A4(0.75,1) B1(-0.75,0.5) B2(-0.25,0.5) B3(0.25,0.5) B4(0.75,0.5) C1(-0.75,0) C2(-0.25,0) C3(0.25,0) C4(0.75,0) D1(-0.75,-0.5) D2(-0.25,-0.5) D3(0.25,-0.5) D4(0.75,-0.5) E1(-0.75,-1) E2(-0.25,-1) E3(0.25,-1) E4(0.75,-1)
Top Overlay:
  circle w0.1: c-1.09,1.34 r0.05
Top Paste:
  drawing of 180 lines, arcs and shapes, not listed
Mechanical 13:
  lines w0.1: -0.985,-1.235 -0.985,1.235 0.985,1.235 0.985,-1.235 -0.985,-1.235
Mechanical 15:
  lines w0.05: -1.085,-1.335 -1.085,1.335 1.085,1.335 1.085,-1.335 -1.085,-1.335
  lines w0.1: -0.5,0 0.5,0 ; 0,-0.5 0,0.5
3D body: height 0.68, standoff 0, extent -0.985,-1.235 0.985,1.235

## TLA3011A [mm] "Micro SMD, 30-Leads, Body 2.97x2.47mm, Pitch 0.5mm, NSC Recommended"
height 0.68
pads (30):
  round 0.265 smd paste-0.132 mask+0.05: A1(-1,1.25) A2(-0.5,1.25) A3(0,1.25) A4(0.5,1.25) A5(1,1.25) B1(-1,0.75) B2(-0.5,0.75) B3(0,0.75) B4(0.5,0.75) B5(1,0.75) C1(-1,0.25) C2(-0.5,0.25) C3(0,0.25) C4(0.5,0.25) C5(1,0.25) D1(-1,-0.25) D2(-0.5,-0.25) D3(0,-0.25) D4(0.5,-0.25) D5(1,-0.25) E1(-1,-0.75) E2(-0.5,-0.75) E3(0,-0.75) E4(0.5,-0.75) E5(1,-0.75) F1(-1,-1.25) F2(-0.5,-1.25) F3(0,-1.25) F4(0.5,-1.25) F5(1,-1.25)
Top Overlay:
  circle w0.1: c-1.34,1.59 r0.05
Top Paste:
  drawing of 270 lines, arcs and shapes, not listed
Mechanical 13:
  lines w0.1: -1.235,-1.485 -1.235,1.485 1.235,1.485 1.235,-1.485 -1.235,-1.485
Mechanical 15:
  lines w0.05: -1.335,-1.585 -1.335,1.585 1.335,1.585 1.335,-1.585 -1.335,-1.585
  lines w0.1: -0.5,0 0.5,0 ; 0,-0.5 0,0.5
3D body: height 0.68, standoff 0, extent -1.235,-1.485 1.235,1.485

## TLC28VFA [mm] "Micro SMD, 28-Leads, Body 3.64x2.45mm, Pitch 0.5mm, NSC Recommended"
height 0.68
pads (28):
  round 0.265 smd paste-0.132 mask+0.05: A1(-0.75,1.464) A2(-0.25,1.464) A3(0.25,1.464) A4(0.75,1.464) B1(-0.75,0.964) B2(-0.25,0.964) B3(0.25,0.964) B4(0.75,0.964) C1(-0.75,0.464) C2(-0.25,0.464) C3(0.25,0.464) C4(0.75,0.464) D1(-0.75,-0.036) D2(-0.25,-0.036) D3(0.25,-0.036) D4(0.75,-0.036) E1(-0.75,-0.536) E2(-0.25,-0.536) E3(0.25,-0.536) E4(0.75,-0.536) F1(-0.75,-1.036) F2(-0.25,-1.036) F3(0.25,-1.036) F4(0.75,-1.036) G1(-0.75,-1.536) G2(-0.25,-1.536) G3(0.25,-1.536) G4(0.75,-1.536)
Top Overlay:
  circle w0.1: c-1.33,1.925 r0.05
Top Paste:
  drawing of 252 lines, arcs and shapes, not listed
Mechanical 13:
  lines w0.1: -1.225,-1.82 1.225,-1.82 1.225,1.82 -1.225,1.82 -1.225,-1.82
Mechanical 15:
  lines w0.05: -1.325,-1.92 1.325,-1.92 1.325,1.92 -1.325,1.92 -1.325,-1.92
  lines w0.1: -0.5,0 0.5,0 ; 0,-0.5 0,0.5
3D body: height 0.68, standoff 0, extent -1.225,-1.82 1.225,1.82

## TLP10A1A [mm] "Micro SMD, 10-Leads, Body 1.97x1.51mm, Pitch 0.5mm, NSC Recommended"
height 0.68
pads (10):
  round 0.265 smd paste-0.132 mask+0.05: A1(-0.5,0.75) A2(0,0.75) A3(0.5,0.75) B1(-0.5,0.25) B3(0.5,0.25) C1(-0.5,-0.25) C3(0.5,-0.25) D1(-0.5,-0.75) D2(0,-0.75) D3(0.5,-0.75)
Top Overlay:
  circle w0.1: c-0.86,1.09 r0.05
Top Paste:
  circle w0.05: c-0.575,0.675 r0.025
  circle w0.05: c-0.425,0.825 r0.025
  circle w0.05: c-0.425,0.675 r0.025
  circle w0.05: c-0.575,0.825 r0.025
  circle w0.05: c-0.075,0.675 r0.025
  circle w0.05: c0.075,0.825 r0.025
  circle w0.05: c0.075,0.675 r0.025
  circle w0.05: c-0.075,0.825 r0.025
  circle w0.05: c0.425,0.675 r0.025
  circle w0.05: c0.575,0.825 r0.025
  circle w0.05: c0.575,0.675 r0.025
  circle w0.05: c0.425,0.825 r0.025
  circle w0.05: c-0.575,0.175 r0.025
  circle w0.05: c-0.425,0.325 r0.025
  circle w0.05: c-0.425,0.175 r0.025
  circle w0.05: c-0.575,0.325 r0.025
  circle w0.05: c0.425,0.175 r0.025
  circle w0.05: c0.575,0.325 r0.025
  circle w0.05: c0.575,0.175 r0.025
  circle w0.05: c0.425,0.325 r0.025
  circle w0.05: c-0.575,-0.325 r0.025
  circle w0.05: c-0.425,-0.175 r0.025
  circle w0.05: c-0.425,-0.325 r0.025
  circle w0.05: c-0.575,-0.175 r0.025
  circle w0.05: c0.425,-0.325 r0.025
  circle w0.05: c0.575,-0.175 r0.025
  circle w0.05: c0.575,-0.325 r0.025
  circle w0.05: c0.425,-0.175 r0.025
  circle w0.05: c-0.575,-0.825 r0.025
  circle w0.05: c-0.425,-0.675 r0.025
  circle w0.05: c-0.425,-0.825 r0.025
  circle w0.05: c-0.575,-0.675 r0.025
  circle w0.05: c-0.075,-0.825 r0.025
  circle w0.05: c0.075,-0.675 r0.025
  circle w0.05: c0.075,-0.825 r0.025
  circle w0.05: c-0.075,-0.675 r0.025
  circle w0.05: c0.425,-0.825 r0.025
  circle w0.05: c0.575,-0.675 r0.025
  circle w0.05: c0.575,-0.825 r0.025
  circle w0.05: c0.425,-0.675 r0.025
  region: -0.575,0.825 -0.575,0.675 -0.425,0.675 -0.425,0.825
  region: -0.575,0.675 -0.575,0.825 -0.625,0.825 -0.625,0.675
  rectangle: -0.575,0.825 -0.425,0.875
  region: -0.425,0.825 -0.425,0.675 -0.375,0.675 -0.375,0.825
  region: -0.425,0.675 -0.575,0.675 -0.575,0.625 -0.425,0.625
  region: -0.075,0.825 -0.075,0.675 0.075,0.675 0.075,0.825
  region: -0.075,0.675 -0.075,0.825 -0.125,0.825 -0.125,0.675
  rectangle: -0.075,0.825 0.075,0.875
  region: 0.075,0.825 0.075,0.675 0.125,0.675 0.125,0.825
  region: 0.075,0.675 -0.075,0.675 -0.075,0.625 0.075,0.625
  region: 0.425,0.825 0.425,0.675 0.575,0.675 0.575,0.825
  region: 0.425,0.675 0.425,0.825 0.375,0.825 0.375,0.675
  rectangle: 0.425,0.825 0.575,0.875
  region: 0.575,0.825 0.575,0.675 0.625,0.675 0.625,0.825
  region: 0.575,0.675 0.425,0.675 0.425,0.625 0.575,0.625
  region: -0.575,0.325 -0.575,0.175 -0.425,0.175 -0.425,0.325
  region: -0.575,0.175 -0.575,0.325 -0.625,0.325 -0.625,0.175
  rectangle: -0.575,0.325 -0.425,0.375
  region: -0.425,0.325 -0.425,0.175 -0.375,0.175 -0.375,0.325
  region: -0.425,0.175 -0.575,0.175 -0.575,0.125 -0.425,0.125
  region: 0.425,0.325 0.425,0.175 0.575,0.175 0.575,0.325
  region: 0.425,0.175 0.425,0.325 0.375,0.325 0.375,0.175
  rectangle: 0.425,0.325 0.575,0.375
  region: 0.575,0.325 0.575,0.175 0.625,0.175 0.625,0.325
  region: 0.575,0.175 0.425,0.175 0.425,0.125 0.575,0.125
  region: -0.575,-0.175 -0.575,-0.325 -0.425,-0.325 -0.425,-0.175
  region: -0.575,-0.325 -0.575,-0.175 -0.625,-0.175 -0.625,-0.325
  rectangle: -0.575,-0.175 -0.425,-0.125
  region: -0.425,-0.175 -0.425,-0.325 -0.375,-0.325 -0.375,-0.175
  region: -0.425,-0.325 -0.575,-0.325 -0.575,-0.375 -0.425,-0.375
  region: 0.425,-0.175 0.425,-0.325 0.575,-0.325 0.575,-0.175
  region: 0.425,-0.325 0.425,-0.175 0.375,-0.175 0.375,-0.325
  rectangle: 0.425,-0.175 0.575,-0.125
  region: 0.575,-0.175 0.575,-0.325 0.625,-0.325 0.625,-0.175
  region: 0.575,-0.325 0.425,-0.325 0.425,-0.375 0.575,-0.375
  region: -0.575,-0.675 -0.575,-0.825 -0.425,-0.825 -0.425,-0.675
  region: -0.575,-0.825 -0.575,-0.675 -0.625,-0.675 -0.625,-0.825
  rectangle: -0.575,-0.675 -0.425,-0.625
  region: -0.425,-0.675 -0.425,-0.825 -0.375,-0.825 -0.375,-0.675
  region: -0.425,-0.825 -0.575,-0.825 -0.575,-0.875 -0.425,-0.875
  region: -0.075,-0.675 -0.075,-0.825 0.075,-0.825 0.075,-0.675
  region: -0.075,-0.825 -0.075,-0.675 -0.125,-0.675 -0.125,-0.825
  rectangle: -0.075,-0.675 0.075,-0.625
  region: 0.075,-0.675 0.075,-0.825 0.125,-0.825 0.125,-0.675
  region: 0.075,-0.825 -0.075,-0.825 -0.075,-0.875 0.075,-0.875
  region: 0.425,-0.675 0.425,-0.825 0.575,-0.825 0.575,-0.675
  region: 0.425,-0.825 0.425,-0.675 0.375,-0.675 0.375,-0.825
  rectangle: 0.425,-0.675 0.575,-0.625
  region: 0.575,-0.675 0.575,-0.825 0.625,-0.825 0.625,-0.675
  region: 0.575,-0.825 0.425,-0.825 0.425,-0.875 0.575,-0.875
Mechanical 13:
  lines w0.1: -0.755,-0.985 -0.755,0.985 0.755,0.985 0.755,-0.985 -0.755,-0.985
Mechanical 15:
  lines w0.05: -0.855,-1.085 -0.855,1.085 0.855,1.085 0.855,-1.085 -0.855,-1.085
  lines w0.1: -0.5,0 0.5,0 ; 0,-0.5 0,0.5
3D body: height 0.68, standoff 0, extent -0.755,-0.985 0.755,0.985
